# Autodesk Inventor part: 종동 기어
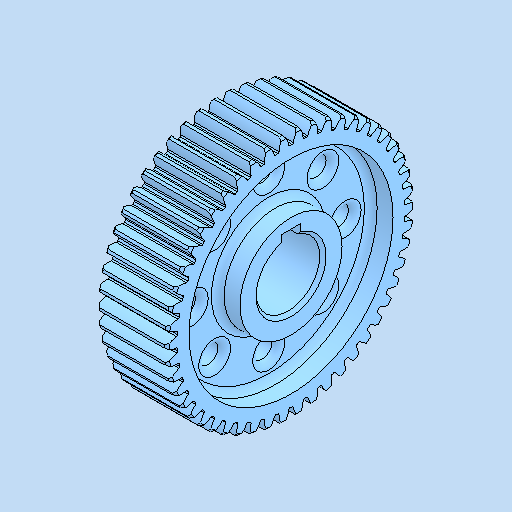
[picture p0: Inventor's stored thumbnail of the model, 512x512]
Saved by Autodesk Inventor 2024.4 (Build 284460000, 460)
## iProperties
Created: 2025-11
Part Number: 종동 기어
Material: 강철, 탄소
Document SubType Name: Modeling
Designer: home
Density: 7.85 g/cm^3
Appearance: 기본값
Author: jhkim
Sending System: Autodesk Inventor 2026
Preprocessor: ST-DEVELOPER v20.1
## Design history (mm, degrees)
feature "솔리드1"
node "솔리드2"
